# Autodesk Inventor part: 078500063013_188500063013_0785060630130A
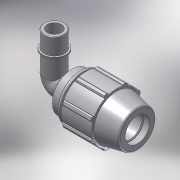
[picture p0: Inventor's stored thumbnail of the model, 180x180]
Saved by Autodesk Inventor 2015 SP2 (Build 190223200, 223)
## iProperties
Created: 2017-02
Part Number: 078500063013_188500063013_0785060630130A
Material: PVC-Piping
Description: PLASSON 90° ELBOW MALE ADAPTOR 63-1.1/4"
Document SubType Name: Modeling
Designer: KIM
Mass: 92.6774 g
Surface Area: 199.44 cm^2
Volume: 66.1981 cm^3
Density: 1.4 g/cm^3
Appearance: Smooth - White
Author: KIM
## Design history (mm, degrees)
derived "07850.ipt"
feature "Solid1::07850.ipt"
tag "TaggingFeature1"
body "Solid1"
other parameters: "d2" = 63, "d4" = 14, "d5" = 42, "d7" = 113, "d9" = 24, "d11" = 5.6, "d13" = 120 deg, "d14" = 81.9, "d15" = 12 deg, "d16" = 98.31, "d18" = 3.15, "d19" = 35 deg, "d20" = 17.5 deg, "d21" = 105.09, "d23" = 0, "d25" = 360 deg, "d27" = 2.26, "d33" = 1.26, "d42" = 62.16, "d43" = 3.39, "d46" = 1.89, "d51" = 168, "d68" = 5.6, "d72" = 76, "d73" = 41.91, "d74" = 22, "d75" = 48.1965, "d76" = 29.337, "d77" = 24.2, "d79" = 16.764, "d80" = 1.2573, "d83" = 0, "d84" = 0, "d91" = 84.75, "d94" = 41.91, "d95" = 29.337, "d96" = 16.8, "d97" = 50 deg, "d_" = 63, "E_" = 113, "A_" = 168, "l_2" = 22, "A_1" = 76, "R_" = 41.91
